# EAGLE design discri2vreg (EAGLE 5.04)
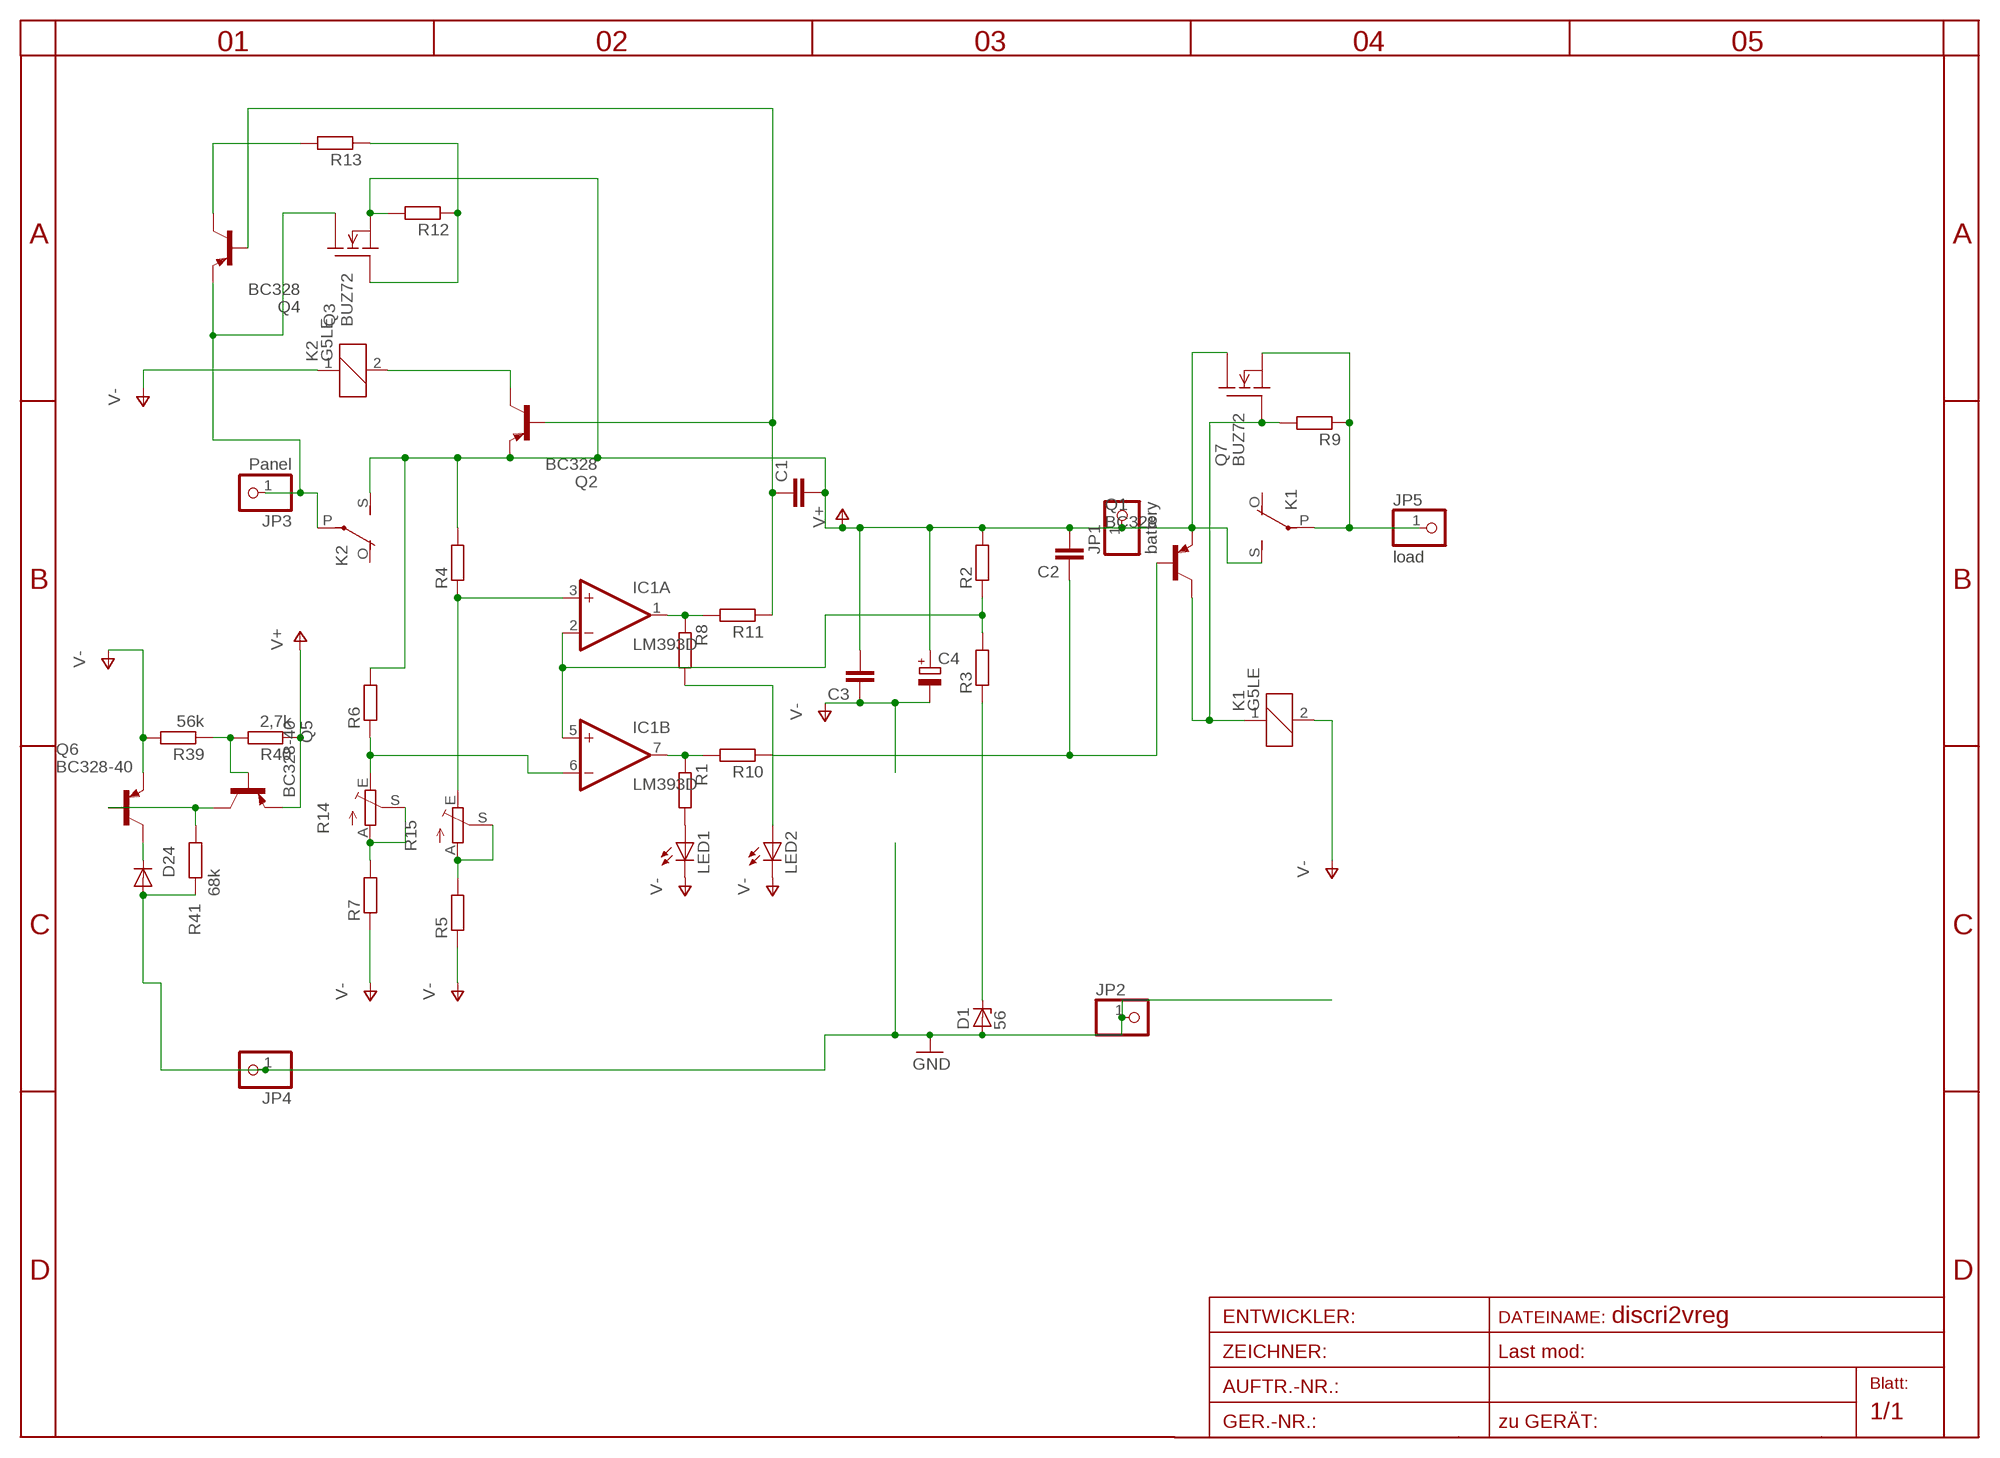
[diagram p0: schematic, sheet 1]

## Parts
C1  C-EU025-025X050  [C025-025X050]
C2  C-EU025-025X050  [C025-025X050]
C3  C-EU025-025X050  [C025-025X050]
C4  CPOL-EU5-13  [2,5-5-FLAT]
D1  56  ZENER-DIODEDO35Z10  [DO35Z10]
D24  Z20  DIODE-D-7.5  [D-7.5]
IC1  LM393D  [SO08]
JP1  battery  PINHD-1X1  [1X01]
JP2  PINHD-1X1  [1X01]
JP3  Panel  PINHD-1X1  [1X01]
JP4  PINHD-1X1  [1X01]
JP5  load  PINHD-1X1  [1X01]
K1  G5LE  [G5LE]
K2  G5LE  [G5LE]
LED1  LED3MM  [LED3MM]
LED2  LED3MM  [LED3MM]
Q1  BC328  [TO92-EBC]
Q2  BC328  [TO92-EBC]
Q3  BUZ72  [TO220]
Q4  BC328  [TO92-EBC]
Q5  BC328-40  [TO92-EBC]
Q6  BC328-40  [TO92-EBC]
Q7  BUZ72  [TO220]
R1  R-EU_0207/15  [0207/15]
R2  R-EU_0204/7  [0204/7]
R3  R-EU_0204/7  [0204/7]
R4  R-EU_0204/7  [0204/7]
R5  R-EU_0204/7  [0204/7]
R6  R-EU_0204/7  [0204/7]
R7  R-EU_0204/7  [0204/7]
R8  R-EU_0207/15  [0207/15]
R9  R-EU_0204/5  [0204/5]
R10  R-EU_0207/15  [0207/15]
R11  R-EU_0204/7  [0204/7]
R12  R-EU_0204/7  [0204/7]
R13  R-EU_0204/7  [0204/7]
R14  TRIM_EU-CA6V  [CA6V]
R15  TRIM_EU-CA6V  [CA6V]
R39  56k  R-EU_0204/7  [0204/7]
R40  2,7k  R-EU_0204/2V  [0204V]
R41  68k  R-EU_0204/7  [0204/7]

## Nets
GND: D1.A D24.A JP2.1 JP4.1 R41.2
LOAD: JP5.1 K1.P(2:P) Q7.3(S) R9.1
N$1: D1.C R3.1
N$2: IC1.6(B:-IN) R6.1 R14.E
N$3: R7.2 R14.A R14.S
N$4: IC1.2(A:-IN) IC1.5(B:+IN) R2.1 R3.2
N$5: K1.1 Q1.C Q7.1(G) R9.2
N$6: LED1.A R1.2
N$7: LED2.A R8.2
N$8: K2.2 Q2.C
N$11: R5.2 R15.A R15.S
N$12: IC1.3(A:+IN) R4.1 R15.E
N$13: D24.C Q6.C
N$14: IC1.1(A:OUT) R8.1 R11.2
N$15: IC1.7(B:OUT) R1.1 R10.2
N$16: C1.1 Q2.B Q4.B R11.1
N$17: C2.1 Q1.B R10.1
N$19: Q3.1(G) R12.1 R13.1
N$20: Q4.C R13.2
N$38: Q5.C Q6.B R41.1
N$41: Q5.B R39.1 R40.2
PANEL: JP3.1 K2.P(2:P) Q3.2(D) Q4.E
V+: C1.2 C2.2 C3.2 C4.+ JP1.1 K1.S(2:S) K2.S(2:S) Q1.E Q2.E Q3.3(S) Q5.E Q7.2(D) R2.2 R4.2 R6.2 R12.2 R40.1
V-: C3.1 C4.- K1.2 K2.1 LED1.K(C) LED2.K(C) Q6.E R5.1 R7.1 R39.2
Unconnected: K1.O(2:O) K2.O(2:O)

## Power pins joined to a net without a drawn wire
V+: IC1.8(P:V+)
V-: IC1.4(P:V-)

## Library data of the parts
C1-C3 = rcl-2:C-EU: CAPACITOR, European symbol
C4 = rcl-2:CPOL-EU: POLARIZED CAPACITOR, European symbol
D1 = diode-1:ZENER-DIODE: Z-Diode
D24 = diode-1:DIODE-: DIODE
IC1 = linear:LM393: COMPARATOR
JP1-JP5 = pinhead:PINHD-1X1: PIN HEADER
K1 K2 = relay2:G5LE: RELAY 1 x switch, 10 A/120 V AC, 8 A/30 V DC, Omron
LED1 LED2 = led:LED: LED
Q1 Q2 Q4-Q6 = transistor-pnp:BC328*: PNP Transistror
Q3 Q7 = transistor-fet:BUZ72: N-Channel Enhancement MOSFET 100V; 10A; 0,2Ohm
R1-R13 R39-R41 = rcl-2:R-EU_: RESISTOR, European symbol
R14 R15 = pot:TRIM_EU-: POTENTIOMETER

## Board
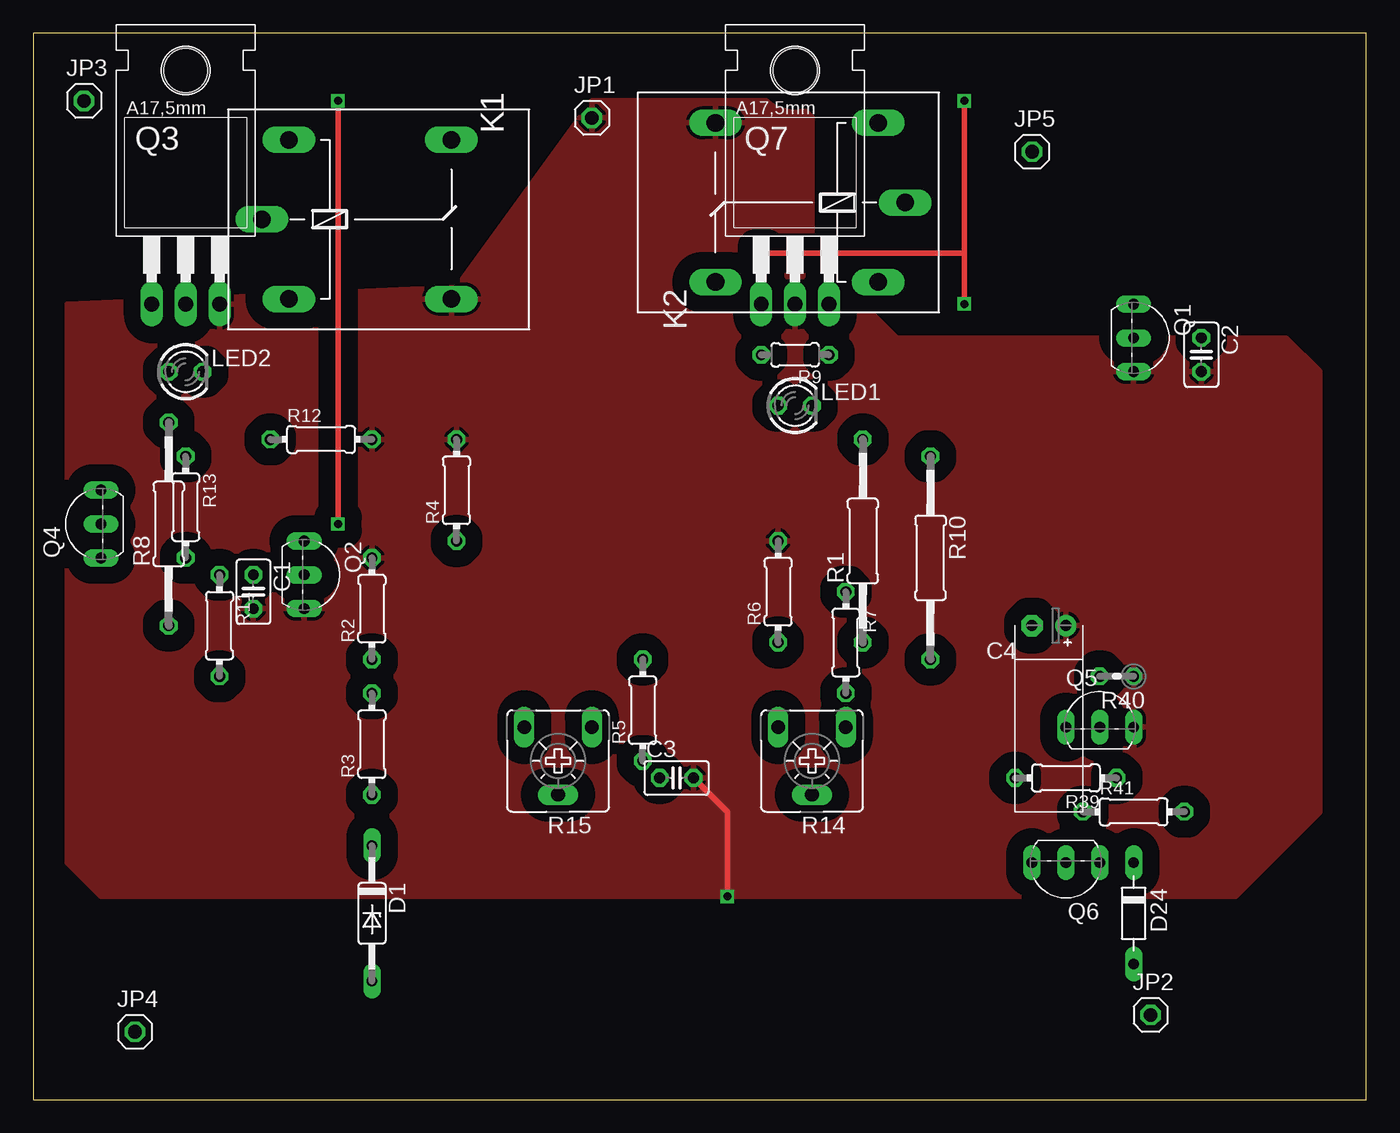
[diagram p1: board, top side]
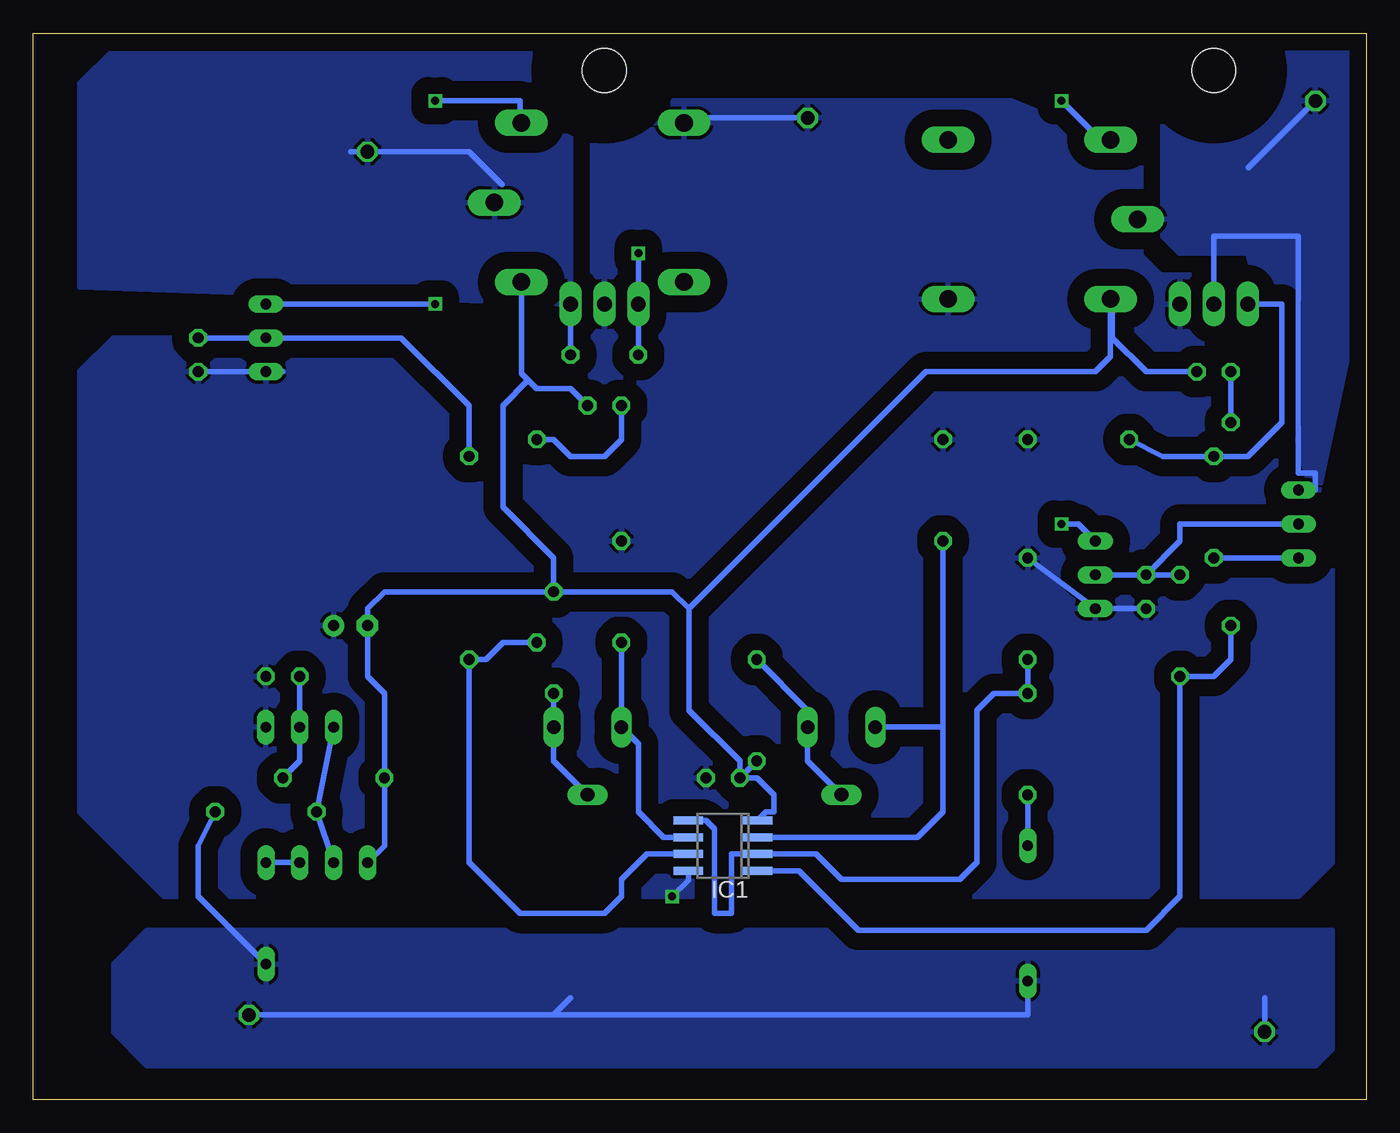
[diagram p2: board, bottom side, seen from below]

Size 100 x 80 mm. Coordinates in mm from the lower left corner, seen from the top.
Outline: 0,0 100,0 100,80 0,80 0,0
Copper layers (1*16): Top 0.035mm / dielectric 1.5mm / Bottom 0.035mm
Design rules "default": minimum track width 10mil, minimum drill 24mil, track to track 8mil, track to pad 8mil, pad to pad 8mil, via to via 8mil, smd to smd 8mil, copper to edge 40mil, drill to drill 8mil, minimum pad ring 10mil, minimum via ring 8mil, stop-mask expansion 4mil, vias tented up to drill 0mil, thermal gap 10mil

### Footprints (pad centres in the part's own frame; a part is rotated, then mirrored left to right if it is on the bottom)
C025-025X050 = drill 0.813 octagon: 1 -1.27,0; 2 1.27,0
2,5-5-FLAT = drill 0.813 pad 1.6 round: + -1.27,0 | drill 0.813 pad 1.6 octagon: - 1.27,0
DO35Z10 = drill 0.813 long: A 5.08,0; C -5.08,0
D-7.5 = drill 0.813 long: A 3.81,0; C -3.81,0
SO08 = smd 0.6 x 2.2: 1 -1.905,-2.6; 2 -0.635,-2.6; 3 0.635,-2.6; 4 1.905,-2.6; 5 1.905,2.6; 6 0.635,2.6; 7 -0.635,2.6; 8 -1.905,2.6
1X01 = drill 1.016 octagon: 1 0,0
G5LE = drill 1.321 long: 1 -7.493,-5.969; 2 -7.493,5.969; O 4.699,5.969; P -9.525,0; S 4.699,-5.969
LED3MM = drill 0.813 octagon: A -1.27,0; K 1.27,0
TO92-EBC = drill 0.813 long: B 0,-1.27; C -2.54,-1.27; E 2.54,-1.27
TO220 = drill 1.118 long: 1 -2.54,-6.35; 2 0,-6.35; 3 2.54,-6.35 | hole 3.302: 0,11.176
0207/15 = drill 0.813 octagon: 1 -7.62,0; 2 7.62,0
0204/7 = drill 0.813 octagon: 1 -3.81,0; 2 3.81,0
0204/5 = drill 0.813 octagon: 1 -2.54,0; 2 2.54,0
CA6V = drill 1.016 long: A -2.54,-2.54; E 2.54,-2.54; S 0,2.54
0204V = drill 0.813 octagon: 1 -1.27,0; 2 1.27,0

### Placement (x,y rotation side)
C1  16.51,38.1 270 top
C2  87.63,55.88 270 top
C3  48.26,24.13 0 top
C4  76.2,35.56 180 top
D1  25.4,13.97 270 top
D24  82.55,13.97 270 top
IC1  48.26,19.05 90 bottom
JP1  41.91,73.66 0 top
JP2  83.82,6.35 0 top
JP3  3.81,74.93 0 top
JP4  7.62,5.08 0 top
JP5  74.93,71.12 0 top
K1  55.88,67.31 180 top
K2  26.67,66.04 0 top
LED1  57.15,52.07 0 top
LED2  11.43,54.61 0 top
Q1  83.82,57.15 270 top
Q2  21.59,39.37 270 top
Q3  11.43,66.04 0 top
Q4  3.81,43.18 90 top
Q5  80.01,29.21 0 top
Q6  77.47,16.51 180 top
Q7  57.15,66.04 0 top
R1  62.23,41.91 90 top
R2  25.4,36.83 90 top
R3  25.4,26.67 90 top
R4  31.75,45.72 90 top
R5  45.72,29.21 90 top
R6  55.88,38.1 90 top
R7  60.96,34.29 270 top
R8  10.16,43.18 90 top
R9  57.15,55.88 180 top
R10  67.31,40.64 270 top
R11  13.97,35.56 270 top
R12  21.59,49.53 0 top
R13  11.43,44.45 270 top
R14  58.42,25.4 180 top
R15  39.37,25.4 180 top
R39  77.47,24.13 180 top
R40  81.28,31.75 180 top
R41  82.55,21.59 0 top

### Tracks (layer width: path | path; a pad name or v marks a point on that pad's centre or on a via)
GND
  Bottom 0.406: 62.23,6.35 60.96,6.35 59.69,7.62 | 62.23,6.35 JP2.1 | D1.A 25.4,6.35 62.23,6.35 | JP4.1 7.62,7.62 | D24.A 87.63,15.24 87.63,19.05 R41.2
  pour Bottom (isolate 1.27, rank 4): 2.54,12.7 91.44,12.7 93.98,10.16 93.98,5.08 91.44,2.54 3.81,2.54 2.54,3.81
LOAD
  Bottom 0.406: 64.83,68.64 67.31,71.12 JP5.1 76.2,71.12 | R9.1 Q7.3
  pour Bottom (isolate 1.27, rank 4): 59.69,76.2 62.23,78.74 93.98,78.74 96.52,76.2 96.52,60.96 59.69,59.69
N$1
  Bottom 0.406: D1.C R3.1
N$2
  Bottom 0.406: R6.1 R14.E 54.61,26.67 54.61,21.59 52.7,19.68 IC1.6
N$3
  Bottom 0.406: R14.S 60.96,25.4 R14.A R7.2
N$4
  Bottom 0.406: R2.1 R3.2 27.94,30.48 29.21,29.21 29.21,17.78 30.48,16.51 39.37,16.51 41.27,18.41 IC1.2 47.62,18.41 47.62,13.97 48.9,13.97 48.9,20.32 49.53,20.95 IC1.5
N$5  (via drill 0.6)
  Top 0.406: 69.85,63.5 v69.85,59.69 | 69.85,63.5 v69.85,74.93 | v54.61,63.5 69.85,63.5
  Bottom 0.406: R9.2 Q7.1 v54.61,63.5 | v69.85,59.69 Q1.C | v69.85,74.93 63.5,74.93 63.5,73.41 K1.1
N$6
  Bottom 0.406: R1.2 60.96,49.53 59.69,48.26 57.15,48.26 55.88,49.53 LED1.A
N$7
  Bottom 0.406: R8.2 LED2.A
N$8  (via drill 0.6)
  Top 0.406: v22.86,43.18 v22.86,74.93
  Bottom 0.406: K2.2 19.94,72.01 v22.86,74.93 | v22.86,43.18 21.59,43.18 Q2.C
N$11
  Bottom 0.406: R15.S 41.91,25.4 R15.A 41.91,29.21 R5.2
N$12
  Bottom 0.406: 31.75,27.94 31.75,21.59 33.66,19.68 IC1.3 | 31.75,27.94 R4.1 | 31.75,27.94 R15.E
N$13
  Bottom 0.406: Q6.C D24.C
N$14
  Bottom 0.406: IC1.1 42.55,17.14 38.1,12.7 16.51,12.7 13.97,15.24 R11.2 11.43,31.75 10.16,33.02 R8.1
N$15
  Bottom 0.406: IC1.7 53.98,18.41 55.88,16.51 55.88,15.24 57.15,13.97 63.5,13.97 67.31,17.78 R10.2 66.04,33.02 64.77,34.29 R1.1
N$16
  Bottom 0.406: Q4.B 13.97,43.18 13.97,41.91 C1.1 | C1.1 R11.1 | C1.1 Q2.B
N$17
  Bottom 0.406: R10.1 67.31,52.07 72.39,57.15 Q1.B C2.1
N$19
  Bottom 0.406: Q3.1 6.35,59.69 6.35,50.8 8.89,48.26 15.24,48.26 | 15.24,48.26 R12.1 | 15.24,48.26 R13.1
N$20
  Bottom 0.406: Q4.C R13.2
N$38
  Bottom 0.406: Q6.B R41.1 Q5.C
N$41
  Bottom 0.406: R39.1 80.01,25.4 Q5.B R40.2
PANEL
  Bottom 0.406: JP3.1 8.83,69.91 | Q3.2 11.43,64.77 5.08,64.77 5.08,46.99 3.81,46.99 3.81,45.72 Q4.E
  pour Bottom (isolate 1.27): 0,80.01 0,62.23 3.81,44.45 8.89,63.5 13.97,63.5 15.24,64.77 15.24,80.01
V+  (via drill 0.6)
  Top 0.406: v52.07,15.24 52.07,21.59 C3.2
  Bottom 0.406: JP1.1 50.8,73.66 K1.S | C2.2 Q1.E 81.28,54.61 | C1.2 Q2.E R2.2 | IC1.8 50.86,16.45 v52.07,15.24
  pour Bottom (isolate 1.27, rank 5): 26.67,74.93 57.15,74.93 58.42,73.66 58.42,63.5 64.77,57.15 93.98,57.15 96.52,54.61 96.52,21.59 90.17,15.24 5.08,15.24 2.54,17.78 2.54,63.5 5.08,66.04
  pour Top (isolate 1.27, rank 5): 41.91,74.93 57.15,74.93 58.42,73.66 58.42,63.5 64.77,57.15 93.98,57.15 96.52,54.61 96.52,21.59 90.17,15.24 5.08,15.24 2.54,17.78 2.54,59.69 31.75,60.96
V-
  Bottom 0.406: K1.2 63.37,54.48 62.87,53.98 | 62.87,53.98 62.23,53.34 59.69,53.34 LED1.K | C3.1 45.72,24.13 44.45,22.86 44.45,21.59 45.02,21.59 IC1.4 | C3.1 R5.1 | C3.1 46.99,25.4 50.8,29.21 50.8,36.83 | 50.8,36.83 52.07,38.1 R7.1 | R7.1 73.66,38.1 74.93,36.83 C4.- 74.93,31.75 73.66,30.48 R39.2 73.66,19.05 Q6.E | LED2.K 16.51,54.61 19.05,57.15 19.05,59.94 K2.1 19.18,55.75 20.32,54.61 33.02,54.61 50.8,36.83 | R7.1 60.96,40.64 64.77,44.45 64.77,52.07 62.87,53.98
